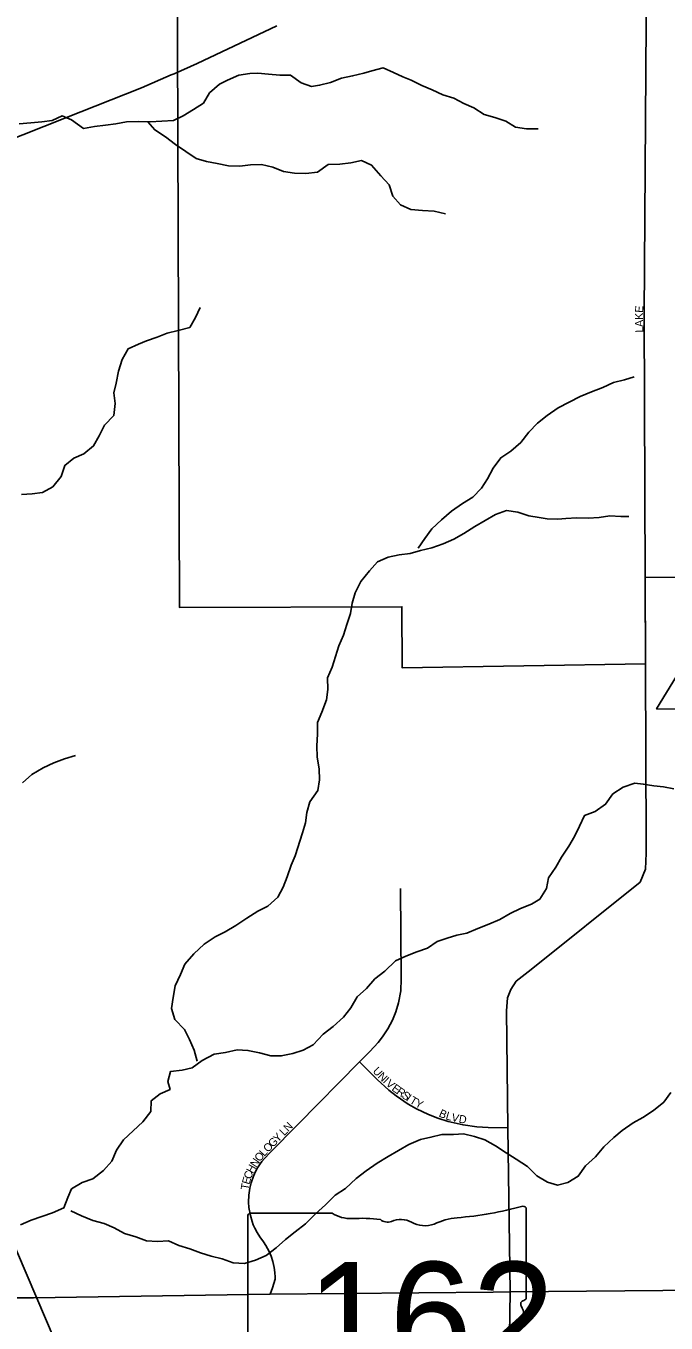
# Model space of a CAD drawing. Extents: x 1985906 to 2277390, y 930619 to 1324581.
# Drawn here: x 2131455 to 2135458, y 1129372 to 1137477 of the extents above; entities that cross this region are included whole.
import ezdxf

# ---------------------------------------------------------------- set-up
doc = ezdxf.new("R2010")
doc.units = 0
for name, color, linetype in [('GM_X_City_Street', 7, 'Continuous'), ('GM_X_City_Street_Text', 7, 'Continuous'), ('GM_X_Corporation', 7, 'Continuous'), ('GM_X_County_Road', 7, 'Continuous'), ('GM_X_Minor_River', 7, 'Continuous'), ('GM_X_Rail_Line', 7, 'Continuous'), ('GM_X_State_Location', 7, 'Continuous'), ('GM_X_State_Route', 7, 'Continuous'), ('GM_X_State_Shield', 7, 'Continuous'), ('GM_X_Township_Subdivision', 7, 'Continuous'), ('GM_X_Township_Subdivision_Text', 7, 'Continuous'), ('GM_X_US_Route', 7, 'Continuous')]:
    doc.layers.add(name, color=color, linetype=linetype)

msp = doc.modelspace()

# ---------------------------------------------------------------- linework, layer by layer
at = {"layer": 'GM_X_City_Street'}
msp.add_lwpolyline([(2135325.8, 1134577), (2135321.8, 1135672.6), (2135334.2, 1137499.7), (2135330.3, 1138144.6)], dxfattribs=at)
at = {"layer": 'GM_X_Corporation'}
msp.add_lwpolyline([(2136709.2, 1138705.4), (2136660.1, 1134644.9), (2135955.2, 1133206.6), (2135398.4, 1133209.2), (2135899.2, 1134027.1), (2135327.8, 1134032.4), (2135329.8, 1133491.3), (2133808.1, 1133465.9), (2133806.7, 1133847.6), (2132416.1, 1133842.6), (2132394.6, 1139746.5)], dxfattribs=at)
at = {"layer": 'GM_X_County_Road'}
for points in [[(2135327.8, 1134052.4), (2135325.9, 1134549.2), (2135325.8, 1134577)], [(2135333.9, 1132373.5), (2135327.9, 1134024.3), (2135327.8, 1134052.4)], [(2134482.4, 1129566.6), (2134469.2, 1130592.4), (2134459.8, 1131322.2), (2134466.6, 1131403.6), (2134486.9, 1131455.6), (2134520.8, 1131507.5), (2134613.4, 1131582.1), (2135295.3, 1132126.9), (2135328.9, 1132207.4), (2135334.2, 1132307.8), (2135334, 1132344.5), (2135333.9, 1132373.5)], [(2134418.2, 1121704.9), (2134431.5, 1123539.5), (2134441.4, 1126876.1), (2134482.4, 1129566.6)]]:
    msp.add_lwpolyline(points, dxfattribs=at)
at = {"layer": 'GM_X_Minor_River'}
for points in [[(2131953.3, 1136857.4), (2132018, 1136866.4), (2132084.5, 1136877.2), (2132156.8, 1136879.9), (2132233.1, 1136878.5), (2132305.5, 1136881.2), (2132377.9, 1136885.9), (2132438.7, 1136914.9), (2132503.7, 1136955.9), (2132566.6, 1136994.9), (2132603.9, 1137058.4), (2132665.1, 1137113.5), (2132715.8, 1137138.7), (2132786.6, 1137169.5), (2132855.1, 1137180.3), (2132905.4, 1137181.4), (2132971.6, 1137176.2), (2133043.8, 1137168.9), (2133110.1, 1137169.7), (2133175.5, 1137122.3), (2133241.4, 1137099.1), (2133291.8, 1137106.2), (2133360.4, 1137123), (2133429.2, 1137149.9), (2133497.7, 1137164.7), (2133568.3, 1137181.5), (2133618.8, 1137196.6), (2133689.4, 1137215.4), (2133753.2, 1137186.1), (2133813, 1137159), (2133864.9, 1137138), (2133930.6, 1137104.7), (2133996.4, 1137077.4), (2134062.2, 1137046.1), (2134130.2, 1137026.9), (2134193.8, 1136991.6), (2134255.7, 1136966.4), (2134321.2, 1136923.1), (2134387.2, 1136905.8), (2134455.1, 1136882.6), (2134516.7, 1136845.3), (2134584.8, 1136834.1), (2134657.2, 1136834.8)], [(2131413.3, 1136865.2), (2131485.7, 1136872), (2131554.1, 1136878.8), (2131618.5, 1136885.6), (2131681.3, 1136914.6), (2131741.2, 1136891.4), (2131814.5, 1136835.9), (2131885.1, 1136848.7), (2131953.3, 1136857.4)], [(2132217.6, 1136878.4), (2132260.4, 1136827.9), (2132327.9, 1136784.5), (2132391.4, 1136737.2), (2132454.9, 1136692), (2132520.4, 1136648.6), (2132584.4, 1136629.4), (2132650.5, 1136618.2), (2132722.5, 1136602.9), (2132792.8, 1136601.6), (2132859.3, 1136608.4), (2132927.6, 1136611.2), (2132999.6, 1136593.8), (2133065.5, 1136568.6), (2133133.6, 1136557.3), (2133205.9, 1136556), (2133278.3, 1136562.7), (2133345.5, 1136611.7), (2133417.8, 1136614.4), (2133486.3, 1136621.2), (2133552.8, 1136636), (2133616.6, 1136606.8), (2133673.7, 1136541.6), (2133727, 1136484.4), (2133749.9, 1136413.8), (2133797.1, 1136358.8), (2133862.9, 1136329.5), (2133935.1, 1136324.2), (2134007.4, 1136320.8), (2134079.4, 1136303.5)], [(2131427.3, 1134549.7), (2131493.6, 1134552.5), (2131558.1, 1134561.4), (2131623, 1134596.3), (2131676.3, 1134661.6), (2131697.6, 1134731.4), (2131754.7, 1134776.5), (2131817.4, 1134803.5), (2131878.5, 1134852.5), (2131913.8, 1134916.1), (2131947.1, 1134981.7), (2132004.4, 1135042.9), (2132013.7, 1135116.9), (2132004.8, 1135185.3), (2132019.9, 1135245.2), (2132033.3, 1135319.2), (2132056.7, 1135393), (2132094, 1135458.6), (2132158.8, 1135489.5), (2132209.3, 1135508.6), (2132276, 1135531.5), (2132338.7, 1135556.5), (2132407.3, 1135573.3), (2132480, 1135592), (2132515.2, 1135655.6), (2132544.4, 1135717.3)], [(2133908.5, 1134214), (2133949.7, 1134273.4), (2133993, 1134334.8), (2134054.3, 1134391.9), (2134115.4, 1134445), (2134184.6, 1134493.9), (2134249.6, 1134532.8), (2134304.8, 1134588), (2134341.9, 1134647.6), (2134377.2, 1134713.1), (2134424.6, 1134778.5), (2134487.6, 1134819.5), (2134550.8, 1134874.5), (2134600.2, 1134939.8), (2134653.3, 1134995), (2134714.4, 1135042.1), (2134783.6, 1135091), (2134852.5, 1135125.9), (2134921.4, 1135162.7), (2134992.3, 1135191.6), (2135063, 1135218.4), (2135129.9, 1135249.3), (2135198.5, 1135266.1), (2135259.1, 1135285.1)], [(2132527, 1131008.8), (2132508.1, 1131077.3), (2132477.1, 1131144.1), (2132446, 1131206.8), (2132386.8, 1131268.1), (2132365.9, 1131336.7), (2132375.2, 1131406.8), (2132388.5, 1131478.7), (2132421.9, 1131550.4), (2132449.1, 1131614.1), (2132504.5, 1131679.3), (2132569.8, 1131740.3), (2132638.9, 1131785.2), (2132701.7, 1131816.2), (2132768.7, 1131855.1), (2132835.8, 1131902), (2132904.8, 1131944.9), (2132967.6, 1131975.9), (2133030.9, 1132032.9), (2133064.2, 1132096.5), (2133089.4, 1132160.3), (2133114.7, 1132232), (2133137.9, 1132291.8), (2133184.6, 1132435.4), (2133203.7, 1132497.3), (2133210.8, 1132561.3), (2133230.1, 1132629.2), (2133279.6, 1132700.5), (2133290.8, 1132766.6), (2133287.9, 1132834.8), (2133277.1, 1132907.2), (2133274.4, 1132979.5), (2133277.6, 1133051.7), (2133278.9, 1133123.9), (2133306.1, 1133189.6), (2133335.6, 1133265.3), (2133342.8, 1133331.4), (2133340, 1133403.7), (2133369.3, 1133469.3), (2133390.5, 1133537.2), (2133411.7, 1133603), (2133441.1, 1133670.7), (2133462.3, 1133736.5), (2133485.6, 1133806.3), (2133494.7, 1133870.3), (2133513.9, 1133934.2), (2133549.3, 1134005.8), (2133602.7, 1134073.1), (2133653.9, 1134128.3), (2133720.7, 1134157.2), (2133789.3, 1134172), (2133857.7, 1134180.8), (2133922.3, 1134199.7), (2133992.9, 1134216.5), (2134063.7, 1134241.3), (2134130.5, 1134270.2), (2134193.4, 1134305.1), (2134262.5, 1134350), (2134327.4, 1134387), (2134392.3, 1134423.9), (2134461, 1134448.8), (2134531.2, 1134439.5), (2134599.1, 1134416.2), (2134665.2, 1134405), (2134715.3, 1134398), (2134781.5, 1134394.8), (2134831.9, 1134399.9), (2134900.2, 1134402.7), (2134970.5, 1134401.5), (2135038.9, 1134406.2), (2135107.3, 1134415), (2135175.6, 1134411.8), (2135225.8, 1134410.9)], [(2131434.2, 1132747.9), (2131493.3, 1132799), (2131562.4, 1132841.9), (2131629.2, 1132872.8), (2131695.9, 1132897.7), (2131764.6, 1132918.5)], [(2134281.1, 1131837.8), (2134349.9, 1131864.6), (2134418.7, 1131893.5), (2134483.6, 1131930.4), (2134548.4, 1131961.4), (2134617.2, 1131990.2), (2134668, 1132021.4), (2134709.3, 1132086.9), (2134722.5, 1132154.8), (2134767.9, 1132220.2), (2134805.1, 1132283.8), (2134850.5, 1132351.2), (2134885.7, 1132412.7), (2134917, 1132476.4), (2134948.3, 1132544), (2135015, 1132568.9), (2135080.1, 1132613.9), (2135125.4, 1132679.2), (2135190.4, 1132720.2), (2135263.1, 1132745), (2135315.3, 1132740), (2135381.4, 1132728.8), (2135441.5, 1132721.7), (2135505.6, 1132710.5)], [(2131420.4, 1129985.5), (2131487.2, 1130014.4), (2131553.8, 1130037.2), (2131622.5, 1130060.1), (2131691.4, 1130090.9), (2131716.6, 1130156.7), (2131739.7, 1130210.4), (2131806.6, 1130249.3), (2131873.3, 1130272.2), (2131940.5, 1130325.2), (2131991.8, 1130384.4), (2132021.1, 1130452.1), (2132066.4, 1130517.5), (2132125.6, 1130572.6), (2132186.9, 1130629.7), (2132236.2, 1130693), (2132239.4, 1130761.2), (2132294.4, 1130804.3), (2132357.1, 1130831.3), (2132341.9, 1130881.7), (2132359.1, 1130943.6), (2132431.6, 1130952.3), (2132494.1, 1130967.2), (2132557.2, 1131012.2), (2132632.2, 1131053), (2132702.7, 1131061.8), (2132775.3, 1131078.5), (2132843.5, 1131075.3), (2132915.6, 1131059.9), (2132987.6, 1131040.6), (2133051.9, 1131041.4), (2133124.4, 1131056.2), (2133189.1, 1131077.1), (2133251.9, 1131110), (2133313.4, 1131177.1), (2133376.5, 1131224.1), (2133441.8, 1131283.2), (2133487, 1131342.5), (2133526.3, 1131410), (2133585.5, 1131463.1), (2133636.8, 1131522.4), (2133699.9, 1131571.4), (2133765.3, 1131634.4), (2133830.1, 1131665.4), (2133898.9, 1131692.2), (2133965.6, 1131715.1), (2134026.6, 1131756.1), (2134089.2, 1131777.1), (2134149.8, 1131796), (2134212.3, 1131808.9), (2134281.1, 1131837.8)], [(2131735.3, 1130072.1), (2131803, 1130042.8), (2131872.8, 1130013.4), (2131944.8, 1129994.1), (2132006.6, 1129966.9), (2132072.3, 1129931.6), (2132142.3, 1129910.2), (2132210.1, 1129884.9), (2132278.4, 1129881.7), (2132346.8, 1129886.5), (2132410.5, 1129857.2), (2132480.5, 1129835.9), (2132546.3, 1129810.7), (2132614.3, 1129789.4), (2132682.3, 1129772.1), (2132750.2, 1129748.8), (2132822.4, 1129743.5), (2132891.1, 1129764.3), (2132957.9, 1129793.2), (2133021, 1129842.2), (2133078.1, 1129893.3), (2133139.2, 1129942.4), (2133202.4, 1129991.4), (2133265.7, 1130054.5), (2133329, 1130111.5), (2133388.3, 1130170.6), (2133453.3, 1130213.6), (2133520.7, 1130274.6), (2133581.8, 1130323.6), (2133650.9, 1130370.5), (2133720, 1130413.4), (2133849.8, 1130487.3), (2133922.7, 1130518.1), (2133987.2, 1130533), (2134055.8, 1130549.8), (2134128.2, 1130550.5), (2134190.5, 1130553.4), (2134260.5, 1130538.1), (2134324.5, 1130516.9), (2134392.1, 1130479.5), (2134457.6, 1130436.2), (2134521.3, 1130396.9), (2134590.7, 1130349.6), (2134650, 1130292.3), (2134715.6, 1130253), (2134779.6, 1130233.8), (2134844.2, 1130250.7), (2134909.1, 1130289.6), (2134954.5, 1130355), (2135017.7, 1130410.1), (2135069, 1130473.3), (2135132.3, 1130530.4), (2135183.3, 1130575.6), (2135252.4, 1130622.5), (2135313.2, 1130655.5), (2135380.3, 1130700.4), (2135443.5, 1130751.5), (2135488.7, 1130812.8)]]:
    msp.add_lwpolyline(points, dxfattribs=at)
at = {"layer": 'GM_X_Rail_Line'}
msp.add_lwpolyline([(2133572.7, 1124731.6), (2133429.5, 1125064.5), (2132764.9, 1126619.2), (2131928.4, 1128579.1), (2131402, 1129810.9), (2131077.9, 1130568.8), (2130884.3, 1131022.3), (2130499.6, 1131921.3), (2130177.2, 1132675.6), (2129985.4, 1133121.6), (2129904.4, 1133293), (2129807, 1133477.2), (2129706.1, 1133652.1), (2129640.3, 1133763.4), (2129579.6, 1133856.1), (2129416.4, 1134092.8), (2129250.3, 1134308.5), (2129140.1, 1134440.8), (2129044.5, 1134548.7), (2128588, 1135044.2), (2128154.3, 1135515.2), (2127609.2, 1136109.3), (2127360.9, 1136377.4), (2127087.5, 1136674.2)], dxfattribs=at)
at = {"layer": 'GM_X_State_Route'}
for points in [[(2134482.4, 1129566.6), (2135677.7, 1129577.9), (2137342.7, 1129596.4), (2138351.4, 1129603.3), (2138906.3, 1129605.5), (2139800.4, 1129668.5), (2140031.3, 1129681.6), (2140403.4, 1129701.2), (2140677.6, 1129703.4), (2141339.2, 1129703.4), (2143801.5, 1129721.9)], [(2124187.8, 1129468.8), (2125742.8, 1129479.4), (2126378.1, 1129482.1), (2130859.2, 1129530.4), (2131503.7, 1129530.4), (2132983.4, 1129551.4), (2134376.8, 1129565.6)], [(2134376.8, 1129565.6), (2134482.4, 1129566.6)]]:
    msp.add_lwpolyline(points, dxfattribs=at)
at = {"layer": 'GM_X_State_Shield'}
for p, q in [((2134583.2, 1129531.4), (2134583.2, 1130084.1)), ((2132843, 1130039.7), (2132843, 1128983.1)), ((2133369.7, 1130057.9), (2132860.1, 1130057.9)), ((2134583, 1129531.5), (2134583.2, 1129531.4))]:
    msp.add_line(p, q, dxfattribs=at)
for centre, major_axis, start_param, end_param in [((2133963.3, 1131498.5), (1845.5, 0), 4.814394, 5.042369), ((2134563.9, 1130086.4), (19.4, 0), 6.141152, 7.989035), ((2132862.9, 1130042), (20.2, 0), 1.712693, 3.28349), ((2133491.1, 1130180.6), (195.5, 0), 4.042523, 4.731795), ((2133555.9, 1129464.7), (702, 0), 1.404758, 1.657858), ((2133715.3, 1130047.5), (56.4, 0), 3.836095, 5.185415), ((2133798.1, 1129925.3), (117.3, 0), 0.950623, 2.079405), ((2133949.5, 1130092.8), (141.1, 0), 4.081561, 5.145723), ((2134198.7, 1129735.2), (371.3, 0), 1.699011, 2.107814), ((2134578.7, 1129490.8), (30, 0), 1.883978, 3.671073), ((2134562.5, 1129529.2), (20.7, 0), 5.05454, 6.418171), ((2134388, 1129420.9), (180, 0), 5.934695, 6.695948)]:
    msp.add_ellipse(centre, major_axis=major_axis, ratio=0.8, start_param=start_param, end_param=end_param, dxfattribs=at)
at = {"layer": 'GM_X_Township_Subdivision'}
for points in [[(2132983.4, 1129551.4), (2132996.6, 1129592.4), (2133014, 1129646.3), (2133013.8, 1129657.7), (2133012.1, 1129686.7), (2133007.8, 1129718.2), (2132999, 1129756.8), (2132988.1, 1129790), (2132976.1, 1129818.3), (2132966.7, 1129837), (2132955, 1129857.4), (2132941.1, 1129878.5), (2132917.9, 1129910.3), (2132901, 1129937.1), (2132886.8, 1129964), (2132877.2, 1129985.8), (2132869.8, 1130005.4), (2132858.6, 1130043.6), (2132850, 1130093.5), (2132847.8, 1130128), (2132849.1, 1130170.7), (2132855.5, 1130215.6), (2132863.3, 1130247.3), (2132878.2, 1130290), (2132891.3, 1130318.4), (2132903.7, 1130340.8), (2132916.8, 1130361.5), (2132931.4, 1130381.6), (2132948.7, 1130402.4), (2132979.6, 1130434.5), (2133155, 1130612.8), (2133540.4, 1131004.2), (2133604.7, 1131069.6), (2133656.9, 1131124.5), (2133685.5, 1131160.3), (2133719.1, 1131211.1), (2133747.1, 1131264.5), (2133768.3, 1131316.4), (2133785.4, 1131373.8), (2133798.6, 1131447.5), (2133802.6, 1131522), (2133797.3, 1132087)], [(2133540.4, 1131004.2), (2133590.9, 1130954.5), (2133652.2, 1130894.3), (2133723.9, 1130827.9), (2133770.9, 1130790.8), (2133845.7, 1130740.3), (2133897.2, 1130710.8), (2133973.3, 1130674.3), (2134031.1, 1130651.6), (2134094.6, 1130631.2), (2134188.2, 1130609.5), (2134275.5, 1130597.5), (2134344.6, 1130593.5), (2134469.2, 1130592.4)]]:
    msp.add_lwpolyline(points, dxfattribs=at)
at = {"layer": 'GM_X_US_Route'}
for points in [[(2132363.4, 1137171), (2132381.5, 1137178.9), (2132526.9, 1137242.1), (2133023.8, 1137477.2)], [(2131689, 1136897.1), (2131698.7, 1136901), (2132178, 1137090.3), (2132363.4, 1137171)], [(2124728.5, 1132501.1), (2124847.5, 1133131.3), (2124877.1, 1133262.7), (2124949.3, 1133392.3), (2124999.2, 1133483), (2125082.5, 1133592.2), (2125147.3, 1133662.5), (2125232.4, 1133754.3), (2125270, 1133784.9), (2125543.2, 1133947.9), (2126424.1, 1134473.5), (2126930.9, 1134814.6), (2127334.4, 1135090.2), (2127621.9, 1135280.7), (2127724.1, 1135333.3), (2128167.2, 1135525.6), (2129051.6, 1135878.2), (2130319, 1136368.7), (2130818.4, 1136553.3), (2131689, 1136897.1)]]:
    msp.add_lwpolyline(points, dxfattribs=at)

# ---------------------------------------------------------------- texts
at = {"layer": 'GM_X_City_Street_Text'}
for s, rotation, p in [('K', 90.37163, (2135313.6, 1135640.5)), ('E', 86.28223, (2135313.3, 1135683.5)), ('A', 91.82956, (2135315, 1135596.8)), ('L', 91.83088, (2135316.1, 1135561.7))]:
    msp.add_text(s, height=50, rotation=rotation, dxfattribs=at).set_placement(p)
at = {"layer": 'GM_X_State_Location'}
for s in ['s', 'r']:
    msp.add_text(s, height=1, dxfattribs=at).set_placement((2133693.5, 1129441.2))
at = {"layer": 'GM_X_State_Shield'}
msp.add_text('162', height=696.1, dxfattribs=at).set_placement((2133209.8, 1129057.6))
at = {"layer": 'GM_X_Township_Subdivision_Text'}
for s, rotation, p in [('U', 312.2634, (2133620.3, 1130944)), ('N', 315.22199, (2133651.9, 1130909.4)), ('I', 316.89551, (2133684.3, 1130877.3)), ('V', 318.79661, (2133701.7, 1130861)), ('E', 323.67557, (2133738.4, 1130829.1)), ('R', 324.70557, (2133767.6, 1130807.7)), ('S', 324.72595, (2133799.9, 1130784.8)), ('I', 324.72149, (2133828.6, 1130764.5)), ('T', 328.52257, (2133849.6, 1130749.8)), ('Y', 333.70676, (2133884, 1130729)), ('B', 335.93394, (2134033.1, 1130664.5)), ('L', 343.79516, (2134076.2, 1130645.8)), ('V', 346.9835, (2134112.8, 1130635.2)), ('D', 350.69122, (2134159.1, 1130624.6)), ('Y', 45.57256, (2133030.5, 1130497.7)), ('L', 45.5795, (2133070.6, 1130538.5)), ('N', 45.57185, (2133095.2, 1130563.7)), ('O', 45.66458, (2132969, 1130434.8)), ('G', 45.57185, (2132999.7, 1130466.2)), ('N', 56.81304, (2132894.6, 1130340.3)), ('O', 51.19342, (2132917.9, 1130376)), ('L', 46.25586, (2132944.8, 1130409.5)), ('C', 70.62057, (2132861.8, 1130267.1)), ('H', 61.44013, (2132874.1, 1130302.5)), ('T', 80.39396, (2132846.9, 1130200.7)), ('E', 74.11464, (2132852.5, 1130234))]:
    msp.add_text(s, height=50, rotation=rotation, dxfattribs=at).set_placement(p)

doc.saveas('drawing.dxf')
